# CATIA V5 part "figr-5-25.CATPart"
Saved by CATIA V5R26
Part number: Part2
Bounding box of the stored display mesh (mm): x -75 to 75, y -62.5 to 62.5, z 0 to 20
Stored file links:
  D:\_Deepak\CATIA\CATIA V5-6R2016_Deepak\Resources\Part files\Partfiles\c05_catia_v5_6r2016_prt\figr-5-25.CATPart
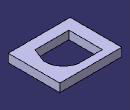
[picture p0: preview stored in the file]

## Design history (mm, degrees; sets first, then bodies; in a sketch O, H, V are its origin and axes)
Body1 (main body)
  Sketch1 on xy-plane, origin (0, 0, 0), H (1, 0, 0), V (0, 1, 0)
    line L1 (-75, 62.5) -> (75, 62.5)
    line L2 (75, 62.5) -> (75, -62.5)
    line L3 (75, -62.5) -> (-75, -62.5)
    line L4 (-75, -62.5) -> (-75, 62.5)
    axis line L5 (75, -62.5) -> (-75, 62.5)
    length L3 = 150
    length L2 = 125
    horizontal: L1 H, L3 H
    vertical: L2 V, L4 V
    midpoint: O L5
  Pad1: profile Sketch1, direction (0, 0, 1), length 20
  Sketch2 on face of Pad1, origin (0, 0, 20), H (1, 0, 0), V (0, 1, 0)
    point P1 (-46.6075, -37.2048)
    line L1 (-46.6075, -37.2048) -> (35.3732, -37.2048)
    point P2 (35.3732, -37.2048)
    point P3 (48.2962, -4.0895)
    line L2 (48.2962, -4.0895) -> (48.2962, 0)
    point P4 (48.2962, 0)
    arc A1 centre (3.919, 0) radius 44.3773 from (48.2962, 0) to (9.9309, 43.9682) ccw
    point P5 (3.919, 0)
    point P6 (9.9309, 43.9682)
    line L3 (9.9309, 43.9682) -> (-46.6075, 43.9682)
    point P7 (-46.6075, 43.9682)
    line L4 (-46.6075, 43.9682) -> (-46.6075, -37.2048)
    line L5 (35.3732, -37.2048) -> (48.2962, -4.0895)
    horizontal: L1 H, L3 H
    coincidence: P4 H
    vertical: L2 V, L4 V
    tangency: A1 L2
    fix: P1, P2, P3, P4, P5, P6, P7, L1, L2, A1, L3, L4, L5
  Pocket1: profile Sketch2, direction (0, 0, -1), through (limit type 3)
